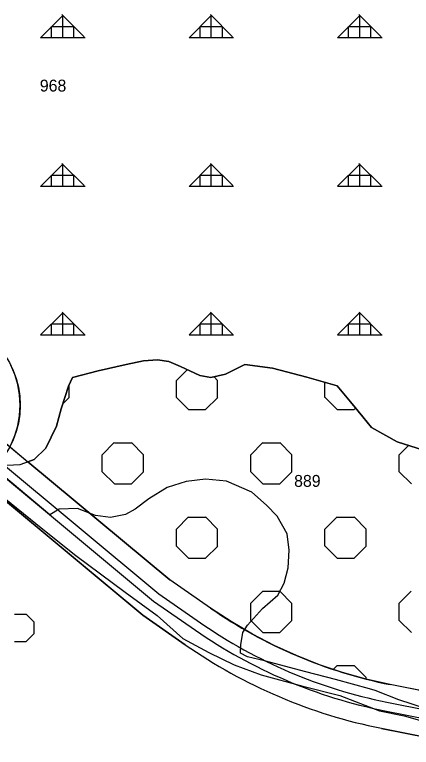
# Model space of a CAD drawing. Extents: x 410727 to 412947, y 4463506 to 4466382.
# Drawn here: x 411696.5 to 411830, y 4465547.1 to 4465793.6 of the extents above; entities that cross this region are included whole.
import ezdxf

# ---------------------------------------------------------------- set-up
doc = ezdxf.new("R2010")
doc.units = 0
for name, color, linetype in [('ADAKENARI', 7, 'Continuous'), ('KALDIRIM', 7, 'Continuous'), ('KAVSAK_BEYAZ', 7, 'Continuous'), ('KD_DAIRE', 7, 'Continuous'), ('KDS_PARSEL_NO', 7, 'Continuous'), ('KDS_PL', 7, 'Continuous'), ('PL_AYA_AGACLANDIRIL', 7, 'Continuous'), ('PL_AYA_ORMAN', 7, 'Continuous'), ('PL_KA_TARIM_DIGER', 7, 'Continuous'), ('TR_AGACALANI', 7, 'Continuous'), ('TR_ORMAN', 7, 'Continuous'), ('TR_TARIMALANI', 7, 'Continuous')]:
    doc.layers.add(name, color=color, linetype=linetype)

msp = doc.modelspace()

# ---------------------------------------------------------------- linework, layer by layer
at = {"layer": 'ADAKENARI'}
for p, q in [((411733.99, 4465675.89), (411724.57, 4465673.73)), ((411739.89, 4465677.14), (411733.99, 4465675.89)), ((411744.54, 4465677.49), (411739.89, 4465677.14)), ((411748.4, 4465676.92), (411744.54, 4465677.49)), ((411752.26, 4465675.21), (411748.4, 4465676.92)), ((411773.93, 4465675.89), (411767.47, 4465672.6)), ((411783.24, 4465674.64), (411773.93, 4465675.89)), ((411724.57, 4465673.73), (411715.95, 4465671.46)), ((411758.84, 4465672.14), (411752.26, 4465675.21)), ((411794.82, 4465671.57), (411783.24, 4465674.64)), ((411715.95, 4465671.46), (411714.58, 4465668.62)), ((411762.47, 4465671.46), (411758.84, 4465672.14)), ((411767.47, 4465672.6), (411762.47, 4465671.46)), ((411805.03, 4465668.73), (411794.82, 4465671.57)), ((411714.58, 4465668.62), (411712.09, 4465661)), ((411809.57, 4465663.27), (411805.03, 4465668.73)), ((411813.66, 4465658.27), (411809.57, 4465663.27)), ((411679.13, 4465661.35), (411700.95, 4465643.19)), ((411712.09, 4465661), (411710.5, 4465655.09)), ((411816.6, 4465654.74), (411813.66, 4465658.27)), ((411710.5, 4465655.09), (411706.98, 4465647.7)), ((411825.23, 4465649.86), (411816.6, 4465654.74)), ((411834.08, 4465647.01), (411825.23, 4465649.86)), ((411706.98, 4465647.7), (411703.01, 4465643.94)), ((411675.96, 4465644.48), (411739.57, 4465591.54)), ((411703.01, 4465643.94), (411700.95, 4465643.19)), ((411700.95, 4465643.19), (411748.66, 4465603.48)), ((411762.45, 4465593.91), (411748.66, 4465603.48)), ((411739.57, 4465591.54), (411753.89, 4465581.59)), ((411860.27, 4465560.72), (411822.91, 4465568.19)), ((411819.96, 4465553.48), (411926.33, 4465532.21)), ((411819.96, 4465553.48), (411926.33, 4465532.21))]:
    msp.add_line(p, q, dxfattribs=at)
for radius in [161.52, 161.52, 176.52, 176.52]:
    msp.add_arc((411854.58, 4465726.58), radius, 235.2222, 258.6901, dxfattribs=at)
at = {"layer": 'KALDIRIM'}
for p, q in [((411673.68, 4465658.08), (411745.02, 4465598.7)), ((411693.39, 4465637.78), (411743.2, 4465596.32)), ((411745.02, 4465598.7), (411759.03, 4465588.98)), ((411743.2, 4465596.32), (411757.32, 4465586.51)), ((411821.73, 4465562.31), (411928.09, 4465541.03)), ((411821.14, 4465559.37), (411927.51, 4465538.09))]:
    msp.add_line(p, q, dxfattribs=at)
for radius in [167.52, 167.52, 170.52, 170.52]:
    msp.add_arc((411854.58, 4465726.58), radius, 235.2222, 258.6901, dxfattribs=at)
at = {"layer": 'KAVSAK_BEYAZ'}
for points in [[(411698.11, 4465658.73), (411698.32, 4465662.21), (411698.11, 4465665.69), (411697.51, 4465669.13), (411696.51, 4465672.47), (411695.13, 4465675.67)], [(411695.13, 4465648.74), (411696.51, 4465651.95), (411697.51, 4465655.29), (411698.11, 4465658.73)]]:
    msp.add_lwpolyline(points, dxfattribs=at)
at = {"layer": 'KD_DAIRE'}
msp.add_circle((411668.32, 4465662.21), 30, dxfattribs=at)
at = {"layer": 'KDS_PL'}
for p, q in [((411724.57, 4465673.73), (411733.99, 4465675.89)), ((411733.99, 4465675.89), (411739.89, 4465677.14)), ((411739.89, 4465677.14), (411744.54, 4465677.49)), ((411744.54, 4465677.49), (411748.4, 4465676.92)), ((411748.4, 4465676.92), (411752.26, 4465675.21)), ((411767.47, 4465672.6), (411773.93, 4465675.89)), ((411773.93, 4465675.89), (411783.24, 4465674.64)), ((411715.95, 4465671.46), (411724.57, 4465673.73)), ((411752.26, 4465675.21), (411758.84, 4465672.14)), ((411783.24, 4465674.64), (411794.82, 4465671.57)), ((411714.58, 4465668.62), (411715.95, 4465671.46)), ((411758.84, 4465672.14), (411762.47, 4465671.46)), ((411762.47, 4465671.46), (411767.47, 4465672.6)), ((411794.82, 4465671.57), (411805.03, 4465668.73)), ((411712.09, 4465661), (411714.58, 4465668.62)), ((411805.03, 4465668.73), (411809.57, 4465663.27)), ((411809.57, 4465663.27), (411813.66, 4465658.27)), ((411710.5, 4465655.09), (411712.09, 4465661)), ((411813.66, 4465658.27), (411816.6, 4465654.74)), ((411706.98, 4465647.7), (411710.5, 4465655.09)), ((411816.6, 4465654.74), (411825.23, 4465649.86)), ((411825.23, 4465649.86), (411834.08, 4465647.01)), ((411703.01, 4465643.94), (411706.98, 4465647.7)), ((411698.35, 4465642.24), (411703.01, 4465643.94)), ((411691.55, 4465641.9), (411698.35, 4465642.24)), ((411708.29, 4465625.33), (411689.77, 4465640.8)), ((411754.19, 4465636.55), (411747.84, 4465634.5)), ((411760.77, 4465637.34), (411754.19, 4465636.55)), ((411767.81, 4465636.66), (411760.77, 4465637.34)), ((411776.32, 4465632.91), (411767.81, 4465636.66)), ((411747.84, 4465634.5), (411741.6, 4465630.64)), ((411781.31, 4465628.59), (411776.32, 4465632.91)), ((411692.94, 4465631.07), (411705.91, 4465620.45)), ((411741.6, 4465630.64), (411737.06, 4465627.22)), ((411711.41, 4465627.22), (411708.29, 4465625.33)), ((411717.65, 4465627.45), (411711.41, 4465627.22)), ((411723.67, 4465625.06), (411717.65, 4465627.45)), ((411737.06, 4465627.22), (411733.77, 4465625.41)), ((411784.83, 4465624.84), (411781.31, 4465628.59)), ((411728.77, 4465624.38), (411723.67, 4465625.06)), ((411733.77, 4465625.41), (411728.77, 4465624.38)), ((411788.24, 4465618.92), (411784.83, 4465624.84)), ((411705.91, 4465620.45), (411717.03, 4465611.68)), ((411788.92, 4465613.47), (411788.24, 4465618.92)), ((411717.03, 4465611.68), (411733.7, 4465599.3)), ((411788.58, 4465607.44), (411788.92, 4465613.47)), ((411787.22, 4465602.32), (411788.58, 4465607.44)), ((411785.06, 4465598.23), (411787.22, 4465602.32)), ((411733.7, 4465599.3), (411744.41, 4465591.46)), ((411779.95, 4465593.79), (411785.06, 4465598.23)), ((411774.85, 4465588.22), (411779.95, 4465593.79)), ((411744.41, 4465591.46), (411753.05, 4465583.73)), ((411773.26, 4465585.72), (411774.85, 4465588.22)), ((411772.58, 4465581.63), (411773.26, 4465585.72)), ((411753.05, 4465583.73), (411761.8, 4465578.99)), ((411772.46, 4465578.79), (411772.58, 4465581.63)), ((411761.8, 4465578.99), (411770.35, 4465574.86)), ((411774.85, 4465577.54), (411772.46, 4465578.79)), ((411780.63, 4465576.17), (411774.85, 4465577.54)), ((411770.35, 4465574.86), (411779.51, 4465571.46)), ((411794.48, 4465572.53), (411780.63, 4465576.17)), ((411804.46, 4465569.92), (411794.48, 4465572.53)), ((411779.51, 4465571.46), (411793.51, 4465567.64)), ((411815.93, 4465566.73), (411804.46, 4465569.92)), ((411793.51, 4465567.64), (411805.96, 4465564.55)), ((411817.86, 4465566.17), (411815.93, 4465566.73)), ((411825.8, 4465563.1), (411817.86, 4465566.17)), ((411805.96, 4465564.55), (411819.34, 4465559.39)), ((411835.1, 4465560.03), (411825.8, 4465563.1)), ((411819.34, 4465559.39), (411827.58, 4465557.64)), ((411827.58, 4465557.64), (411846.83, 4465552.17))]:
    msp.add_line(p, q, dxfattribs=at)
at = {"layer": 'PL_AYA_AGACLANDIRIL'}
msp.add_lwpolyline([(411860.27, 4465560.72), (411822.91, 4465568.19), (411814.84, 4465570.02), (411806.88, 4465572.26), (411799.05, 4465574.9), (411791.36, 4465577.94), (411783.83, 4465581.37), (411776.49, 4465585.18), (411769.36, 4465589.37), (411762.45, 4465593.91), (411748.66, 4465603.48), (411700.95, 4465643.19), (411703.01, 4465643.94), (411706.98, 4465647.7), (411710.5, 4465655.09), (411712.09, 4465661), (411714.58, 4465668.62), (411715.95, 4465671.46), (411724.57, 4465673.73), (411733.99, 4465675.89), (411739.89, 4465677.14), (411744.54, 4465677.49), (411748.4, 4465676.92), (411752.26, 4465675.21), (411758.84, 4465672.14), (411762.47, 4465671.46), (411767.47, 4465672.6), (411773.93, 4465675.89), (411783.24, 4465674.64), (411794.82, 4465671.57), (411805.03, 4465668.73), (411809.57, 4465663.27), (411813.66, 4465658.27), (411816.6, 4465654.74), (411825.23, 4465649.86), (411834.08, 4465647.01)], dxfattribs=at)
at = {"layer": 'PL_AYA_ORMAN'}
msp.add_lwpolyline([(411679.13, 4465661.35), (411700.95, 4465643.19), (411703.01, 4465643.94), (411706.98, 4465647.7), (411710.5, 4465655.09), (411712.09, 4465661), (411714.58, 4465668.62), (411715.95, 4465671.46), (411724.57, 4465673.73), (411733.99, 4465675.89), (411739.89, 4465677.14), (411744.54, 4465677.49), (411748.4, 4465676.92), (411752.26, 4465675.21), (411758.84, 4465672.14), (411762.47, 4465671.46), (411767.47, 4465672.6), (411773.93, 4465675.89), (411783.24, 4465674.64), (411794.82, 4465671.57), (411805.03, 4465668.73), (411809.57, 4465663.27), (411813.66, 4465658.27), (411816.6, 4465654.74), (411825.23, 4465649.86), (411834.08, 4465647.01)], dxfattribs=at)
at = {"layer": 'PL_KA_TARIM_DIGER'}
for points in [[(411753.89, 4465581.59), (411739.57, 4465591.54), (411706.25, 4465619.27), (411675.96, 4465644.48)], [(411926.33, 4465532.21), (411819.96, 4465553.48)]]:
    msp.add_lwpolyline(points, dxfattribs=at)
msp.add_arc((411854.58, 4465726.58), 176.52, 235.2222, 258.6901, dxfattribs=at)
at = {"layer": 'TR_AGACALANI'}
for p, q in [((411750.95, 4465670.54), (411754.56, 4465674.14)), ((411764.81, 4465670.53), (411763.62, 4465671.72)), ((411714.81, 4465664.8), (411714.81, 4465669.1)), ((411750.95, 4465664.8), (411750.95, 4465670.54)), ((411764.81, 4465664.8), (411764.81, 4465670.54)), ((411800.95, 4465664.8), (411800.95, 4465669.87)), ((411712.59, 4465662.53), (411714.83, 4465664.78)), ((411755.03, 4465660.72), (411750.97, 4465664.78)), ((411760.77, 4465660.72), (411764.83, 4465664.78)), ((411805.03, 4465660.72), (411800.97, 4465664.78)), ((411755.03, 4465660.72), (411760.77, 4465660.72)), ((411805.03, 4465660.72), (411810.77, 4465660.72)), ((411810.77, 4465660.72), (411811.26, 4465661.2)), ((411725.95, 4465645.54), (411730.01, 4465649.6)), ((411730.03, 4465649.58), (411735.77, 4465649.58)), ((411739.81, 4465645.53), (411735.75, 4465649.59)), ((411775.95, 4465645.54), (411780.01, 4465649.6)), ((411780.03, 4465649.58), (411785.77, 4465649.58)), ((411789.81, 4465645.53), (411785.75, 4465649.59)), ((411825.95, 4465645.54), (411829.04, 4465648.63)), ((411725.95, 4465639.8), (411725.95, 4465645.54)), ((411739.81, 4465639.8), (411739.81, 4465645.54)), ((411775.95, 4465639.8), (411775.95, 4465645.54)), ((411789.81, 4465639.8), (411789.81, 4465645.54)), ((411825.95, 4465639.8), (411825.95, 4465645.54)), ((411730.03, 4465635.72), (411725.97, 4465639.78)), ((411735.77, 4465635.72), (411739.83, 4465639.78)), ((411780.03, 4465635.72), (411775.97, 4465639.78)), ((411785.77, 4465635.72), (411789.83, 4465639.78)), ((411830.03, 4465635.72), (411825.97, 4465639.78)), ((411730.03, 4465635.72), (411735.77, 4465635.72)), ((411780.03, 4465635.72), (411785.77, 4465635.72)), ((411750.95, 4465620.54), (411755.01, 4465624.6)), ((411755.03, 4465624.58), (411760.77, 4465624.58)), ((411764.81, 4465620.53), (411760.75, 4465624.59)), ((411800.95, 4465620.54), (411805.01, 4465624.6)), ((411805.03, 4465624.58), (411810.77, 4465624.58)), ((411814.81, 4465620.53), (411810.75, 4465624.59)), ((411750.95, 4465614.8), (411750.95, 4465620.54)), ((411764.81, 4465614.8), (411764.81, 4465620.54)), ((411800.95, 4465614.8), (411800.95, 4465620.54)), ((411814.81, 4465614.8), (411814.81, 4465620.54)), ((411755.03, 4465610.72), (411750.97, 4465614.78)), ((411760.77, 4465610.72), (411764.83, 4465614.78)), ((411805.03, 4465610.72), (411800.97, 4465614.78)), ((411810.77, 4465610.72), (411814.83, 4465614.78)), ((411755.03, 4465610.72), (411760.77, 4465610.72)), ((411805.03, 4465610.72), (411810.77, 4465610.72)), ((411775.95, 4465595.54), (411780.01, 4465599.6)), ((411780.03, 4465599.58), (411785.77, 4465599.58)), ((411789.81, 4465595.53), (411785.75, 4465599.59)), ((411825.95, 4465595.54), (411830.01, 4465599.6)), ((411775.95, 4465589.8), (411775.95, 4465595.54)), ((411789.81, 4465589.8), (411789.81, 4465595.54)), ((411825.95, 4465589.8), (411825.95, 4465595.54)), ((411780.03, 4465585.72), (411775.97, 4465589.78)), ((411785.77, 4465585.72), (411789.83, 4465589.78)), ((411830.03, 4465585.72), (411825.97, 4465589.78)), ((411780.03, 4465585.72), (411785.77, 4465585.72)), ((411803.73, 4465573.32), (411805.01, 4465574.6)), ((411805.03, 4465574.58), (411810.77, 4465574.58)), ((411814.81, 4465570.53), (411810.75, 4465574.59)), ((411814.81, 4465570.03), (411814.81, 4465570.54))]:
    msp.add_line(p, q, dxfattribs=at)
at = {"layer": 'TR_ORMAN'}
for p, q in [((411705.17, 4465785.81), (411712.67, 4465793.31)), ((411719.87, 4465786.08), (411712.37, 4465793.58)), ((411712.67, 4465785.86), (411712.67, 4465793.36)), ((411755.17, 4465785.81), (411762.67, 4465793.31)), ((411769.86, 4465786.08), (411762.36, 4465793.58)), ((411762.67, 4465785.86), (411762.67, 4465793.36)), ((411805.17, 4465785.82), (411812.66, 4465793.32)), ((411819.85, 4465786.08), (411812.35, 4465793.58)), ((411819.85, 4465786.08), (411812.35, 4465793.58)), ((411812.67, 4465785.86), (411812.67, 4465793.36)), ((411708.92, 4465785.86), (411708.92, 4465789.61)), ((411708.92, 4465789.61), (411716.42, 4465789.61)), ((411716.42, 4465785.86), (411716.42, 4465789.61)), ((411758.92, 4465785.86), (411758.92, 4465789.61)), ((411758.92, 4465789.61), (411766.42, 4465789.61)), ((411766.42, 4465785.86), (411766.42, 4465789.61)), ((411808.92, 4465785.86), (411808.92, 4465789.61)), ((411808.92, 4465789.61), (411816.42, 4465789.61)), ((411816.42, 4465785.86), (411816.42, 4465789.61)), ((411705.17, 4465785.86), (411720.17, 4465785.86)), ((411755.17, 4465785.86), (411770.17, 4465785.86)), ((411805.17, 4465785.86), (411820.17, 4465785.86)), ((411705.17, 4465735.81), (411712.67, 4465743.31)), ((411719.9, 4465736.06), (411712.4, 4465743.55)), ((411712.67, 4465735.86), (411712.67, 4465743.36)), ((411755.17, 4465735.82), (411762.67, 4465743.32)), ((411769.89, 4465736.06), (411762.39, 4465743.55)), ((411762.67, 4465735.86), (411762.67, 4465743.36)), ((411805.17, 4465735.83), (411812.66, 4465743.33)), ((411819.88, 4465736.06), (411812.38, 4465743.55)), ((411812.67, 4465735.86), (411812.67, 4465743.36)), ((411708.92, 4465735.86), (411708.92, 4465739.61)), ((411708.92, 4465739.61), (411716.42, 4465739.61)), ((411716.42, 4465735.86), (411716.42, 4465739.61)), ((411758.92, 4465735.86), (411758.92, 4465739.61)), ((411758.92, 4465739.61), (411766.42, 4465739.61)), ((411766.42, 4465735.86), (411766.42, 4465739.61)), ((411808.92, 4465735.86), (411808.92, 4465739.61)), ((411808.92, 4465739.61), (411816.42, 4465739.61)), ((411816.42, 4465735.86), (411816.42, 4465739.61)), ((411705.17, 4465735.86), (411720.17, 4465735.86)), ((411755.17, 4465735.86), (411770.17, 4465735.86)), ((411805.17, 4465735.86), (411820.17, 4465735.86)), ((411705.17, 4465685.82), (411712.67, 4465693.32)), ((411705.17, 4465685.82), (411712.67, 4465693.32)), ((411719.93, 4465686.03), (411712.43, 4465693.53)), ((411719.93, 4465686.03), (411712.43, 4465693.53)), ((411712.67, 4465685.86), (411712.67, 4465693.36)), ((411712.67, 4465685.86), (411712.67, 4465693.36)), ((411755.17, 4465685.83), (411762.67, 4465693.33)), ((411755.17, 4465685.83), (411762.67, 4465693.33)), ((411769.92, 4465686.03), (411762.42, 4465693.53)), ((411769.92, 4465686.03), (411762.42, 4465693.53)), ((411762.67, 4465685.86), (411762.67, 4465693.36)), ((411762.67, 4465685.86), (411762.67, 4465693.36)), ((411805.17, 4465685.84), (411812.66, 4465693.34)), ((411805.17, 4465685.84), (411812.66, 4465693.34)), ((411819.91, 4465686.03), (411812.42, 4465693.53)), ((411819.91, 4465686.03), (411812.42, 4465693.53)), ((411812.67, 4465685.86), (411812.67, 4465693.36)), ((411812.67, 4465685.86), (411812.67, 4465693.36)), ((411708.92, 4465685.86), (411708.92, 4465689.61)), ((411708.92, 4465689.61), (411716.42, 4465689.61)), ((411708.92, 4465685.86), (411708.92, 4465689.61)), ((411708.92, 4465689.61), (411716.42, 4465689.61)), ((411716.42, 4465685.86), (411716.42, 4465689.61)), ((411716.42, 4465685.86), (411716.42, 4465689.61)), ((411758.92, 4465685.86), (411758.92, 4465689.61)), ((411758.92, 4465689.61), (411766.42, 4465689.61)), ((411758.92, 4465685.86), (411758.92, 4465689.61)), ((411758.92, 4465689.61), (411766.42, 4465689.61)), ((411766.42, 4465685.86), (411766.42, 4465689.61)), ((411766.42, 4465685.86), (411766.42, 4465689.61)), ((411808.92, 4465685.86), (411808.92, 4465689.61)), ((411808.92, 4465689.61), (411816.42, 4465689.61)), ((411808.92, 4465685.86), (411808.92, 4465689.61)), ((411808.92, 4465689.61), (411816.42, 4465689.61)), ((411816.42, 4465685.86), (411816.42, 4465689.61)), ((411816.42, 4465685.86), (411816.42, 4465689.61)), ((411705.17, 4465685.86), (411720.17, 4465685.86)), ((411705.17, 4465685.86), (411720.17, 4465685.86)), ((411755.17, 4465685.86), (411770.17, 4465685.86)), ((411755.17, 4465685.86), (411770.17, 4465685.86)), ((411805.17, 4465685.86), (411820.17, 4465685.86)), ((411805.17, 4465685.86), (411820.17, 4465685.86))]:
    msp.add_line(p, q, dxfattribs=at)
at = {"layer": 'TR_TARIMALANI'}
for p, q in [((411696.46, 4465591.9), (411700.29, 4465591.9)), ((411696.46, 4465591.9), (411700.29, 4465591.9)), ((411702.99, 4465589.19), (411700.28, 4465591.9)), ((411702.99, 4465589.19), (411700.28, 4465591.9)), ((411703, 4465585.36), (411703, 4465589.19)), ((411703, 4465585.36), (411703, 4465589.19)), ((411700.28, 4465582.65), (411702.99, 4465585.36)), ((411700.28, 4465582.65), (411702.99, 4465585.36)), ((411696.46, 4465582.65), (411700.29, 4465582.65)), ((411696.46, 4465582.65), (411700.29, 4465582.65))]:
    msp.add_line(p, q, dxfattribs=at)

# ---------------------------------------------------------------- texts
at = {"layer": 'KDS_PARSEL_NO'}
for s, p in [('968', (411704.93, 4465767.71)), ('889', (411790.55, 4465634.72))]:
    msp.add_text(s, height=4, dxfattribs=at).set_placement(p)

doc.saveas('drawing.dxf')
